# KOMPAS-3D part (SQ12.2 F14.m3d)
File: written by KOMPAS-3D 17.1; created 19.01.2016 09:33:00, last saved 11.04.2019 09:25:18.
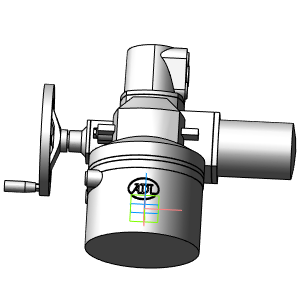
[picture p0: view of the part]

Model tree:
1. Операция без истории:3  (labels: Сталь 20  ГОСТ 1050-88)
